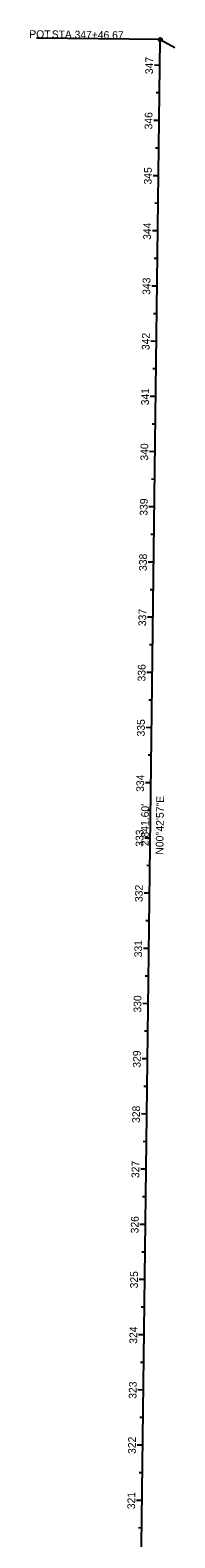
# Model space of a CAD drawing. Extents: x 1652268 to 1652613, y 604222 to 609731.
# Drawn here: x 1652350 to 1652613, y 606999 to 609731 of the extents above; entities that cross this region are included whole.
import ezdxf

# ---------------------------------------------------------------- set-up
doc = ezdxf.new("R2010")
doc.units = 0
for name, color, linetype in [('DT_X_Contour_Major', 7, 'Continuous'), ('DT_X_Contour_Minor', 7, 'Continuous'), ('DT_X_Contour_Text', 7, 'Continuous'), ('DT_X_Terrain_Ground_Line', 7, 'Continuous'), ('DT_X_Triangles', 7, 'Continuous'), ('PV_X_Curb', 7, 'Continuous')]:
    doc.layers.add(name, color=color, linetype=linetype)

msp = doc.modelspace()

# ---------------------------------------------------------------- linework, layer by layer
at = {"layer": 'DT_X_Contour_Minor'}
msp.add_line((1652586.4, 609713.4), (1652361.4, 609716.3), dxfattribs=at)
msp.add_circle((1652586.4, 609713.4), 3, dxfattribs=at)
at = {"layer": 'DT_X_Contour_Text'}
for p, q in [((1652585.8, 609666.8), (1652575.8, 609666.9)), ((1652585.1, 609616.8), (1652579.1, 609616.9)), ((1652584.5, 609566.8), (1652574.5, 609566.9)), ((1652583.9, 609516.8), (1652577.9, 609516.9)), ((1652583.3, 609466.8), (1652573.3, 609466.9)), ((1652582.6, 609416.8), (1652576.6, 609416.9)), ((1652582, 609366.8), (1652572, 609366.9)), ((1652581.4, 609316.8), (1652575.4, 609316.9)), ((1652580.8, 609266.8), (1652570.8, 609266.9)), ((1652580.1, 609216.8), (1652574.1, 609216.9)), ((1652579.5, 609166.8), (1652569.5, 609166.9)), ((1652578.9, 609116.8), (1652572.9, 609116.9)), ((1652578.3, 609066.8), (1652568.3, 609067)), ((1652577.7, 609016.8), (1652571.7, 609016.9)), ((1652577, 608966.8), (1652567, 608967)), ((1652576.4, 608916.8), (1652570.4, 608916.9)), ((1652575.8, 608866.8), (1652565.8, 608867)), ((1652575.2, 608816.8), (1652569.2, 608816.9)), ((1652574.5, 608766.9), (1652564.5, 608767)), ((1652573.9, 608716.9), (1652567.9, 608716.9)), ((1652573.3, 608666.9), (1652563.3, 608667)), ((1652572.7, 608616.9), (1652566.7, 608616.9)), ((1652572, 608566.9), (1652562, 608567)), ((1652571.4, 608516.9), (1652565.4, 608516.9)), ((1652570.8, 608466.9), (1652560.8, 608467)), ((1652570.2, 608416.9), (1652564.2, 608417)), ((1652569.5, 608366.9), (1652559.5, 608367)), ((1652568.9, 608316.9), (1652562.9, 608317)), ((1652568.3, 608266.9), (1652558.3, 608267)), ((1652567.7, 608216.9), (1652561.7, 608217)), ((1652567, 608166.9), (1652557, 608167)), ((1652566.4, 608116.9), (1652560.4, 608117)), ((1652565.8, 608066.9), (1652555.8, 608067)), ((1652565.2, 608016.9), (1652559.2, 608017)), ((1652564.5, 607966.9), (1652554.5, 607967)), ((1652563.9, 607916.9), (1652557.9, 607917)), ((1652563.3, 607866.9), (1652553.3, 607867)), ((1652562.7, 607816.9), (1652556.7, 607817)), ((1652562, 607766.9), (1652552, 607767.1)), ((1652561.4, 607716.9), (1652555.4, 607717)), ((1652560.8, 607666.9), (1652550.8, 607667.1)), ((1652560.2, 607616.9), (1652554.2, 607617)), ((1652559.5, 607566.9), (1652549.5, 607567.1)), ((1652558.9, 607516.9), (1652552.9, 607517)), ((1652558.3, 607467), (1652548.3, 607467.1)), ((1652557.7, 607417), (1652551.7, 607417)), ((1652557, 607367), (1652547, 607367.1)), ((1652556.4, 607317), (1652550.4, 607317)), ((1652555.8, 607267), (1652545.8, 607267.1)), ((1652555.2, 607217), (1652549.2, 607217)), ((1652554.5, 607167), (1652544.5, 607167.1)), ((1652553.9, 607117), (1652547.9, 607117.1)), ((1652553.3, 607067), (1652543.3, 607067.1)), ((1652552.7, 607017), (1652546.7, 607017.1))]:
    msp.add_line(p, q, dxfattribs=at)
at = {"layer": 'DT_X_Terrain_Ground_Line'}
msp.add_line((1652550.9, 606872.1), (1652586.4, 609713.4), dxfattribs=at)
at = {"layer": 'PV_X_Curb'}
msp.add_line((1652586.4, 609713.4), (1652612.9, 609699.2), dxfattribs=at)

# ---------------------------------------------------------------- texts
at = {"layer": 'DT_X_Contour_Major'}
msp.add_text("2,841.60'", height=14, rotation=89.2843, dxfattribs=at).set_placement((1652565, 608252.3))
at = {"layer": 'DT_X_Contour_Minor'}
for s, p in [('POT', (1652348.5, 609716.6)), (' STA. ', (1652384.1, 609716.2)), ('347+46.67', (1652430.7, 609715.6))]:
    msp.add_text(s, height=14, rotation=359.2843, dxfattribs=at).set_placement(p)
at = {"layer": 'DT_X_Contour_Text'}
for s, p in [('347', (1652573.1, 609650.7)), ('346', (1652571.8, 609550.7)), ('345', (1652570.6, 609450.9)), ('344', (1652569.3, 609350.6)), ('343', (1652568.1, 609251)), ('342', (1652566.8, 609150.9)), ('341', (1652565.6, 609050.9)), ('340', (1652564.3, 608950.7)), ('339', (1652563.1, 608850.9)), ('338', (1652561.8, 608750.8)), ('337', (1652560.6, 608650.8)), ('336', (1652559.3, 608550.7)), ('335', (1652558.1, 608451)), ('334', (1652556.8, 608350.6)), ('333', (1652555.6, 608251.1)), ('332', (1652554.3, 608151)), ('331', (1652553.1, 608050.9)), ('330', (1652551.8, 607950.7)), ('329', (1652550.6, 607850.9)), ('328', (1652549.3, 607750.8)), ('327', (1652548.1, 607650.9)), ('326', (1652546.8, 607550.8)), ('325', (1652545.6, 607451.1)), ('324', (1652544.3, 607350.7)), ('323', (1652543.1, 607251.1)), ('322', (1652541.8, 607151.1)), ('321', (1652540.6, 607051))]:
    msp.add_text(s, height=14, rotation=89.2843, dxfattribs=at).set_placement(p)
at = {"layer": 'DT_X_Triangles'}
msp.add_text('N00°42\'57"E', height=14, rotation=89.2843, dxfattribs=at).set_placement((1652591.9, 608236.9))

doc.saveas('drawing.dxf')
